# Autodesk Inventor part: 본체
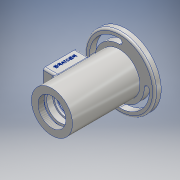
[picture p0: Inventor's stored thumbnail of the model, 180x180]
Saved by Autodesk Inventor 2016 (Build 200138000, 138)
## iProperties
Created: 2017-05
Part Number: 본체
Material: 알루미늄 6061
Document SubType Name: Modeling
Designer: USER
Density: 2.7 g/cm^3
Appearance: 알루미늄 - 평지
Mass: 673.236 g
Surface Area: 619.691 cm^2
Volume: 249.347 cm^3
Author: USER
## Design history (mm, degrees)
sketch "스케치1"
  geometry: C1 r 53 at (0, 0); 1 further point
  constraints: 1 centre point, 1 coincident
  dimensions: "d0" = 106 diameter of C1
extrude "돌출1" new body sketch "스케치1" distance "d1" = 10; taper "d2" = 0 deg
sketch "스케치2"
  geometry: C1 r 31 at (0, 0); 1 further point
  constraints: 1 centre point, 1 coincident
  dimensions: "d3" = 62 diameter of C1
extrude "돌출2" join sketch "스케치2" distance "d4" = 3; taper "d5" = 0 deg
sketch "스케치3"
  geometry: C1 r 31 at (0, 0); 1 further point
  constraints: 1 centre point, 1 coincident
  dimensions: "d6" = 62 diameter of C1
extrude "돌출3" join sketch "스케치3" distance "d7" = 102; taper "d8" = 0 deg
sketch "스케치4"
  geometry: L1 (0, 0)-(0, -177.717); L2 (-31, -112)-(31, -112) reference; L3 (-21, -112)-(-21, -103); L4 (-21, -103)-(-24, -103); L5 (-24, -103)-(-24, -100); L6 (-24, -100)-(-20, -100); L7 (-20, -100)-(-20, -91); L8 (-20, -91)-(-17.5, -91); L9 (-17.5, -91)-(-17.5, -87.75); L10 (-17.5, -87.75)-(-18.5, -87.75); L11 (-18.5, -87.75)-(-18.5, -86); L12 (-18.5, -86)-(-17.5, -86); L13 (31, 3)-(-31, 3) reference; L14 (-22.005, 3)-(-21.985, 3); L15 (-17.5, -75)-(-17.5, -86); L16 (0, 0)-(0, 7.987); L17 (-17.5, -75)-(-26, -75); L18 (-26, -75)-(-26, -37); L19 (-26, -37)-(-17.5, -37); L20 (-17.5, -37)-(-17.5, -26); L21 (-17.5, -26)-(-16.5, -26); L22 (-16.5, -26)-(-16.5, -21); L23 (-16.5, -21)-(-10, -21); L24 (-12.5, -11.7)-(-12.8, -11); L25 (-12.8, -11)-(-16, -11); L26 (-16, -11)-(-22, 3); L27 (-10, -21)-(-10, -18.3); L28 (-10, -18.3)-(-12.5, -18.3); L29 (-12.5, -18.3)-(-12.5, -11.7); L30 (-21, -112)-(0, -112); L31 (0, 3)-(-22, 3); L32 (0, -112)-(0, 3); 1 further point
  constraints: 60 end point, 14 perpendicular, 7 vertical, 6 point on line, 2 collinear, 2 horizontal, 2 midpoint, 2 parallel, 1 horizontal alignment
  dimensions: "d11" = 42 diameter of L3 L1; "d12" = 48 diameter of L5 L1; "d13" = 9 distance of L3.start L3.end; "d14" = 3 distance of L4.end L5.end; "d15" = 21 distance from line of L3.start L8; "d16" = 26 distance from line of L3.start L12; "d17" = 1.75 distance of L10.end L11.end; "d18" = 37 diameter of L11 L1; "d20" = 35 diameter of L9 L1; "d35" = 11 distance of L15.start L12.end; "d40" = 35 diameter of L15 L1; "d52" = 52 diameter of L18 L1; "d53" = 38 distance of L17.end L18.end; "d54" = 11 distance of L19.end L20.end; "d55" = 44 diameter of L26.end L16; "d56" = 32 diameter of L25.end L1; "d57" = 0.7 vertical distance of L24.start L24.end; "d59" = 35 diameter of L20 L1; "d60" = 33 diameter of L22 L1; "d61" = 24 distance from line of L14.end L23; "d62" = 20 diameter of L27 L1; "d63" = 25 diameter of L29 L1; "d64" = 7.3 distance between parallel lines of L28 L25; "d65" = 2.7 distance of L23.end L27.end; "d115" = 20 distance between parallel lines of L32 L7
revolve "회전1" sketch "스케치4" stored, may be unused: angle "d66" = 90 deg
node "작업 평면1"
sketch "스케치5"
  geometry: L1 (-81, -20)-(-31, -20); L2 (-31, -20)-(-31, 20); L3 (-31, 20)-(-81, 20); L4 (-81, 20)-(-81, -20); L5 (-112, 31)-(-112, -31) reference; 2 further points
  constraints: 8 end point, 2 parallel, 1 horizontal, 1 horizontal alignment, 1 midpoint, 1 perpendicular
  dimensions: "d68" = 40 distance between parallel lines of L3 L1; "d69" = 50 distance of L1.start L1.end; "d70" = 31 distance between parallel lines of L5 L4
extrude "돌출4" join sketch "스케치5" stored distance "d71" = 102; taper "d72" = 0 deg
sketch "스케치6"
  geometry: L1 (-11, -72)-(11, -72); L2 (11, -72)-(11, -40); L3 (11, -40)-(-11, -40); L4 (-11, -40)-(-11, -72); L5 (-11, -56)-(11, -56); L6 (-31, -112)-(31, -112) reference; 2 further points
  constraints: 10 end point, 3 midpoint, 2 parallel, 1 horizontal, 1 perpendicular, 1 vertical alignment
  dimensions: "d73" = 32 distance of L3.end L1.start; "d74" = 22 distance of L2.end L3.end; "d75" = 56 distance from line of L6 L5.start
extrude "돌출5" cut sketch "스케치6" stored distance "d76" = 102; taper "d77" = 0 deg
sketch "스케치7"
  geometry: A1 r 41.5 centre (0, 0) between (41.5, 0) and (0, 41.5); A2 r 45.5 centre (0, 0) between (45.5, 0) and (0, 45.5); A3 r 37.5 centre (0, 0) between (37.5, 0) and (0, 37.5); A4 r 4 centre (41.5, 0) between (37.5, 0) and (45.5, 0); A5 r 4 centre (0, 41.5) between (0, 45.5) and (0, 37.5); A6 r 41.5 centre (0, 0) between (-41.5, 0) and (0, -41.5); A7 r 45.5 centre (0, 0) between (-45.5, 0) and (0, -45.5); A8 r 37.5 centre (0, 0) between (-37.5, 0) and (0, -37.5); A9 r 4 centre (-41.5, 0) between (-37.5, 0) and (-45.5, 0); A10 r 4 centre (0, -41.5) between (0, -45.5) and (0, -37.5); 1 further point
  constraints: 20 point on circle, 10 centre point, 8 tangent, 2 coincident, 2 horizontal alignment, 2 vertical alignment
  dimensions: "d78" = 45.5 radius of A2; "d79" = 37.5 radius of A3; "d80" = 37.5 radius of A8; "d81" = 45.5 radius of A7
extrude "돌출6" cut sketch "스케치7" stored distance "d82" = 0; taper "d83" = 0 deg
fillet "모깎기1" dims "d84" = 3
fillet "모깎기2" dims "d85" = 3
chamfer "모따기1" distance "d86" = 1; stored, may be unused: second distance "d87" = 2, angle "d88" = 45 deg
fillet "모깎기3" dims "d89" = 3
fillet "모깎기4" dims "d90" = 3
sketch "스케치8"
  geometry: L1 (-26, -75)-(26, -75) reference; L2 (17, -81)-(-17, -81) reference; L3 (-20, -78)-(-20, -34) reference; L4 (20, -34)-(20, -78) reference; L5 (-17, -31)-(17, -31) reference; 5 further points
  constraints: 2 horizontal alignment, 2 vertical alignment
  dimensions: "d92" = 4.5 distance from line of L2 point (-15.5, -76.5); "d93" = 4.5 distance from line of L3 point (-15.5, -76.5); "d94" = 4.5 distance from line of L4 point (15.5, -76.5); "d95" = 4.5 distance from line of L5 point (15.5, -35.5)
hole "구멍1" sketch "스케치8" at (-15.5, -35.5), (15.5, -35.5), (-15.5, -76.5), (15.5, -76.5) diameter "d96" = 2.459; stored, may be unused: countersink angle "d100" = 90 deg, drill point angle "d102" = 118 deg; dims "d97" = 6, "d98" = 4, "d99" = 2, "d101" = 8
fillet "모깎기5" dims "d103" = 0.3
fillet "모깎기6" dims "d104" = 3
chamfer "모따기2" distance "d105" = 1; stored, may be unused: second distance "d106" = 2, angle "d107" = 45 deg
fillet "모깎기7" dims "d108" = 3
feature "스레드1" dims "d109" = 10, "d110" = 0
sketch "스케치9"
  geometry: L1 (13, -34)-(75, -34) reference; L2 (0, 44)-(0, 0) reference; 2 further points
  constraints: 1 other
  dimensions: "d111" = 56 distance from line of L1 point (8, 22); "d112" = 8 distance from line of L2 point (8, 22)
feature "엠보싱1" sketch "스케치9" dims "d113" = 0.5, "d114" = 0
fillet "모깎기9" dims "d117" = 0.3
node "솔리드1"
other parameters: "d67" = -44
